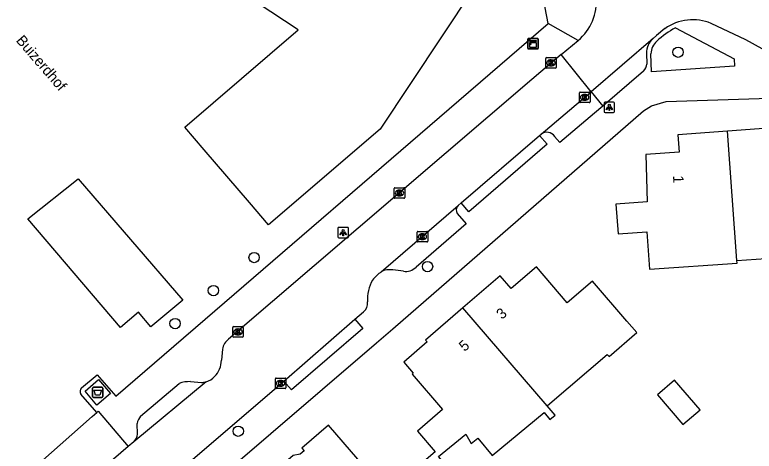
# Model space of a CAD drawing. Extents: x 161772 to 163123, y 383092 to 383917.
# Drawn here: x 162365 to 162435.2, y 383442.3 to 383483.7 of the extents above; entities that cross this region are included whole.
import ezdxf

# ---------------------------------------------------------------- set-up
doc = ezdxf.new("R2010")
doc.units = 0
for name, color, linetype in [('IMGEO_Afval_apart_plaats', 7, 'Continuous'), ('IMGEO_Boom', 7, 'Continuous'), ('IMGEO_Kast', 7, 'Continuous'), ('IMGEO_Kolk', 7, 'Continuous'), ('IMGEO_Lichtpunt', 7, 'Continuous'), ('IMGEO_Openbare_ruimte_label', 7, 'Continuous'), ('IMGEO_Pand', 7, 'Continuous'), ('IMGEO_Pand_nummerreeks', 7, 'Continuous'), ('IMGEO_Parkeervlak_open', 7, 'Continuous'), ('IMGEO_Rijbaan_lokaal_open', 7, 'Continuous'), ('IMGEO_Voetpad_gesloten', 7, 'Continuous'), ('IMGEO_Voetpad_open', 7, 'Continuous')]:
    doc.layers.add(name, color=color, linetype=linetype)

msp = doc.modelspace()

# ---------------------------------------------------------------- linework, layer by layer
at = {"layer": 'IMGEO_Afval_apart_plaats'}
for p, q in [((162372.391, 383447.489), (162372.391, 383448.289)), ((162372.391, 383448.289), (162372.391, 383447.489)), ((162372.491, 383448.389), (162373.281, 383448.389)), ((162373.281, 383448.389), (162372.491, 383448.389)), ((162373.381, 383448.289), (162373.381, 383447.489)), ((162373.381, 383447.489), (162373.381, 383448.289)), ((162373.281, 383447.389), (162372.491, 383447.389)), ((162372.491, 383447.389), (162373.281, 383447.389))]:
    msp.add_line(p, q, dxfattribs=at)
msp.add_lwpolyline([(162372.534, 383448.103), (162373.238, 383448.103), (162373.089, 383447.633), (162372.683, 383447.633), (162372.534, 383448.103)], dxfattribs=at)
for centre, start, end in [((162372.491, 383448.289), 90, 180), ((162372.491, 383448.289), 90, 180), ((162373.281, 383448.289), 0, 90), ((162373.281, 383448.289), 360, 90), ((162372.491, 383447.489), 180, 270), ((162372.491, 383447.489), 180, 270), ((162373.281, 383447.489), 270, 0), ((162373.281, 383447.489), 270, 0)]:
    msp.add_arc(centre, 0.1, start, end, dxfattribs=at)
at = {"layer": 'IMGEO_Boom'}
for centre in [(162427.934, 383480.13), (162387.719, 383460.671), (162404.167, 383459.81), (162383.853, 383457.532), (162380.217, 383454.408), (162386.214, 383444.207)]:
    msp.add_circle(centre, 0.489, dxfattribs=at)
at = {"layer": 'IMGEO_Kast'}
for p, q in [((162413.672, 383480.516), (162413.672, 383481.357)), ((162413.672, 383481.357), (162413.672, 383480.516)), ((162413.747, 383481.441), (162414.588, 383481.441)), ((162414.588, 383481.441), (162413.747, 383481.441)), ((162414.672, 383481.366), (162414.672, 383480.525)), ((162414.672, 383480.525), (162414.672, 383481.366)), ((162414.597, 383480.441), (162413.756, 383480.441)), ((162413.756, 383480.441), (162414.597, 383480.441))]:
    msp.add_line(p, q, dxfattribs=at)
for points in [[(162413.867, 383481.231), (162414.467, 383481.231), (162414.467, 383481.146), (162413.867, 383481.146), (162413.867, 383481.231)], [(162413.867, 383481.056), (162414.467, 383481.056), (162414.467, 383480.567), (162413.867, 383480.567), (162413.867, 383481.056)]]:
    msp.add_lwpolyline(points, dxfattribs=at)
msp.add_circle((162413.951, 383480.905), 0.0377, dxfattribs=at)
for centre, start, end in [((162413.75, 383481.363), 92.4484, 184.28452), ((162413.75, 383481.363), 92.4484, 184.28452), ((162414.594, 383481.363), 2.4484, 94.28452), ((162414.594, 383481.363), 2.4484, 94.28452), ((162413.75, 383480.519), 182.4484, 274.28452), ((162413.75, 383480.519), 182.4484, 274.28452), ((162414.594, 383480.519), 272.4484, 4.28452), ((162414.594, 383480.519), 272.4484, 4.28452)]:
    msp.add_arc(centre, 0.0779, start, end, dxfattribs=at)
at = {"layer": 'IMGEO_Kolk'}
for p, q in [((162415.38, 383478.699), (162415.38, 383479.551)), ((162415.455, 383479.625), (162416.307, 383479.625)), ((162415.868, 383479.405), (162415.893, 383479.405)), ((162416.381, 383479.551), (162416.381, 383478.699)), ((162416.307, 383478.625), (162415.455, 383478.625)), ((162415.891, 383478.845), (162415.866, 383478.845)), ((162418.656, 383476.354), (162419.508, 383476.354)), ((162418.581, 383475.428), (162418.581, 383476.28)), ((162419.069, 383476.134), (162419.094, 383476.134)), ((162419.582, 383476.28), (162419.582, 383475.428)), ((162419.508, 383475.354), (162418.656, 383475.354)), ((162419.092, 383475.574), (162419.067, 383475.574)), ((162401.078, 383467.286), (162401.93, 383467.286)), ((162401.003, 383466.36), (162401.003, 383467.212)), ((162401.491, 383467.066), (162401.516, 383467.066)), ((162402.004, 383467.212), (162402.004, 383466.36)), ((162401.93, 383466.286), (162401.078, 383466.286)), ((162401.514, 383466.506), (162401.489, 383466.506)), ((162403.183, 383462.225), (162403.183, 383463.077)), ((162403.258, 383463.151), (162404.11, 383463.151)), ((162404.184, 383463.077), (162404.184, 383462.225)), ((162403.694, 383462.371), (162403.669, 383462.371)), ((162403.671, 383462.931), (162403.696, 383462.931)), ((162404.11, 383462.151), (162403.258, 383462.151)), ((162385.69, 383453.198), (162385.69, 383454.05)), ((162385.765, 383454.124), (162386.617, 383454.124)), ((162386.178, 383453.904), (162386.203, 383453.904)), ((162386.691, 383454.05), (162386.691, 383453.198)), ((162386.201, 383453.344), (162386.176, 383453.344)), ((162386.617, 383453.124), (162385.765, 383453.124)), ((162389.731, 383448.315), (162389.731, 383449.167)), ((162389.806, 383449.241), (162390.658, 383449.241)), ((162390.219, 383449.021), (162390.244, 383449.021)), ((162390.732, 383449.167), (162390.732, 383448.315)), ((162390.242, 383448.461), (162390.217, 383448.461)), ((162390.658, 383448.241), (162389.806, 383448.241))]:
    msp.add_line(p, q, dxfattribs=at)
for points in [[(162415.38, 383478.699), (162415.38, 383479.551)], [(162415.455, 383479.625), (162416.307, 383479.625)], [(162415.701, 383479.325), (162415.824, 383479.325), (162415.824, 383479.174), (162415.954, 383479.325), (162416.118, 383479.325), (162415.972, 383479.174), (162416.125, 383478.925), (162415.973, 383478.925), (162415.888, 383479.089), (162415.824, 383479.022), (162415.824, 383478.925), (162415.701, 383478.925), (162415.701, 383479.325)], [(162416.381, 383479.551), (162416.381, 383478.699)], [(162416.307, 383478.625), (162415.455, 383478.625)], [(162418.656, 383476.354), (162419.508, 383476.354)], [(162418.581, 383475.428), (162418.581, 383476.28)], [(162418.902, 383476.054), (162419.025, 383476.054), (162419.025, 383475.903), (162419.155, 383476.054), (162419.319, 383476.054), (162419.173, 383475.903), (162419.326, 383475.654), (162419.174, 383475.654), (162419.089, 383475.818), (162419.025, 383475.751), (162419.025, 383475.654), (162418.902, 383475.654), (162418.902, 383476.054)], [(162419.582, 383476.28), (162419.582, 383475.428)], [(162419.508, 383475.354), (162418.656, 383475.354)], [(162401.078, 383467.286), (162401.93, 383467.286)], [(162401.003, 383466.36), (162401.003, 383467.212)], [(162401.324, 383466.986), (162401.447, 383466.986), (162401.447, 383466.835), (162401.577, 383466.986), (162401.741, 383466.986), (162401.595, 383466.835), (162401.748, 383466.586), (162401.596, 383466.586), (162401.511, 383466.75), (162401.447, 383466.683), (162401.447, 383466.586), (162401.324, 383466.586), (162401.324, 383466.986)], [(162402.004, 383467.212), (162402.004, 383466.36)], [(162401.93, 383466.286), (162401.078, 383466.286)], [(162403.183, 383462.225), (162403.183, 383463.077)], [(162403.258, 383463.151), (162404.11, 383463.151)], [(162404.184, 383463.077), (162404.184, 383462.225)], [(162403.504, 383462.851), (162403.627, 383462.851), (162403.627, 383462.7), (162403.757, 383462.851), (162403.921, 383462.851), (162403.775, 383462.7), (162403.928, 383462.451), (162403.776, 383462.451), (162403.691, 383462.615), (162403.627, 383462.548), (162403.627, 383462.451), (162403.504, 383462.451), (162403.504, 383462.851)], [(162404.11, 383462.151), (162403.258, 383462.151)], [(162385.69, 383453.198), (162385.69, 383454.05)], [(162385.765, 383454.124), (162386.617, 383454.124)], [(162386.691, 383454.05), (162386.691, 383453.198)], [(162386.011, 383453.824), (162386.134, 383453.824), (162386.134, 383453.673), (162386.264, 383453.824), (162386.428, 383453.824), (162386.282, 383453.673), (162386.435, 383453.424), (162386.283, 383453.424), (162386.198, 383453.588), (162386.134, 383453.521), (162386.134, 383453.424), (162386.011, 383453.424), (162386.011, 383453.824)], [(162386.617, 383453.124), (162385.765, 383453.124)], [(162389.731, 383448.315), (162389.731, 383449.167)], [(162389.806, 383449.241), (162390.658, 383449.241)], [(162390.732, 383449.167), (162390.732, 383448.315)], [(162390.052, 383448.941), (162390.175, 383448.941), (162390.175, 383448.79), (162390.305, 383448.941), (162390.469, 383448.941), (162390.323, 383448.79), (162390.476, 383448.541), (162390.324, 383448.541), (162390.239, 383448.705), (162390.175, 383448.638), (162390.175, 383448.541), (162390.052, 383448.541), (162390.052, 383448.941)], [(162390.658, 383448.241), (162389.806, 383448.241)]]:
    msp.add_lwpolyline(points, dxfattribs=at)
for centre, start, end in [((162415.457, 383479.549), 91.55205, 178.44795), ((162415.457, 383479.549), 91.55205, 178.44795), ((162416.305, 383479.549), 1.55205, 88.44795), ((162416.305, 383479.549), 1.55205, 88.44795), ((162415.457, 383478.701), 181.55205, 268.44795), ((162415.457, 383478.701), 181.55205, 268.44795), ((162416.305, 383478.701), 271.55205, 358.44795), ((162416.305, 383478.701), 271.55205, 358.44795), ((162418.658, 383476.278), 91.55205, 178.44795), ((162418.658, 383476.278), 91.55205, 178.44795), ((162419.506, 383476.278), 1.55205, 88.44795), ((162419.506, 383476.278), 1.55205, 88.44795), ((162418.658, 383475.43), 181.55205, 268.44795), ((162418.658, 383475.43), 181.55205, 268.44795), ((162419.506, 383475.43), 271.55205, 358.44795), ((162419.506, 383475.43), 271.55205, 358.44795), ((162401.08, 383467.21), 91.55205, 178.44795), ((162401.08, 383467.21), 91.55205, 178.44795), ((162401.928, 383467.21), 1.55205, 88.44795), ((162401.928, 383467.21), 1.55205, 88.44795), ((162401.08, 383466.362), 181.55205, 268.44795), ((162401.08, 383466.362), 181.55205, 268.44795), ((162401.928, 383466.362), 271.55205, 358.44795), ((162401.928, 383466.362), 271.55205, 358.44795), ((162403.26, 383463.075), 91.55205, 178.44795), ((162403.26, 383463.075), 91.55205, 178.44795), ((162404.108, 383463.075), 1.55205, 88.44795), ((162404.108, 383463.075), 1.55205, 88.44795), ((162403.26, 383462.227), 181.55205, 268.44795), ((162403.26, 383462.227), 181.55205, 268.44795), ((162404.108, 383462.227), 271.55205, 358.44795), ((162404.108, 383462.227), 271.55205, 358.44795), ((162385.767, 383454.048), 91.55205, 178.44795), ((162385.767, 383454.048), 91.55205, 178.44795), ((162386.615, 383454.048), 1.55205, 88.44795), ((162386.615, 383454.048), 1.55205, 88.44795), ((162385.767, 383453.2), 181.55205, 268.44795), ((162385.767, 383453.2), 181.55205, 268.44795), ((162386.615, 383453.2), 271.55205, 358.44795), ((162386.615, 383453.2), 271.55205, 358.44795), ((162389.808, 383449.165), 91.55205, 178.44795), ((162389.808, 383449.165), 91.55205, 178.44795), ((162390.656, 383449.165), 1.55205, 88.44795), ((162390.656, 383449.165), 1.55205, 88.44795), ((162389.808, 383448.317), 181.55205, 268.44795), ((162389.808, 383448.317), 181.55205, 268.44795), ((162390.656, 383448.317), 271.55205, 358.44795), ((162390.656, 383448.317), 271.55205, 358.44795)]:
    msp.add_arc(centre, 0.0765, start, end, dxfattribs=at)
for centre, major_axis, ratio, start_param, end_param in [((162415.867, 383479.125), (-0.387, 0.002), 0.722429, 4.712389, 7.853982), ((162415.892, 383479.125), (-0.39, 0.002), 0.717154, 1.570796, 4.712389), ((162419.068, 383475.854), (-0.387, 0.002), 0.722429, 4.712389, 7.853982), ((162419.093, 383475.854), (-0.39, 0.002), 0.717154, 1.570796, 4.712389), ((162401.49, 383466.786), (-0.387, 0.002), 0.722429, 4.712389, 7.853982), ((162401.515, 383466.786), (-0.39, 0.002), 0.717154, 1.570796, 4.712389), ((162403.67, 383462.651), (-0.387, 0.002), 0.722429, 4.712389, 7.853982), ((162403.695, 383462.651), (-0.39, 0.002), 0.717154, 1.570796, 4.712389), ((162386.177, 383453.624), (-0.387, 0.002), 0.722429, 4.712389, 7.853982), ((162386.202, 383453.624), (-0.39, 0.002), 0.717154, 1.570796, 4.712389), ((162390.218, 383448.741), (-0.387, 0.002), 0.722429, 4.712389, 7.853982), ((162390.243, 383448.741), (-0.39, 0.002), 0.717154, 1.570796, 4.712389)]:
    msp.add_ellipse(centre, major_axis=major_axis, ratio=ratio, start_param=start_param, end_param=end_param, dxfattribs=at)
at = {"layer": 'IMGEO_Lichtpunt'}
for p, q in [((162420.912, 383475.308), (162420.912, 383474.501)), ((162420.912, 383475.308), (162420.912, 383474.501)), ((162421.814, 383475.403), (162421.006, 383475.403)), ((162421.814, 383475.403), (162421.006, 383475.403)), ((162421.908, 383474.501), (162421.908, 383475.308)), ((162421.908, 383474.501), (162421.908, 383475.308)), ((162421.006, 383474.407), (162421.814, 383474.407)), ((162421.006, 383474.407), (162421.814, 383474.407)), ((162395.663, 383463.434), (162395.663, 383462.627)), ((162395.663, 383463.434), (162395.663, 383462.627)), ((162396.565, 383463.529), (162395.757, 383463.529)), ((162396.565, 383463.529), (162395.757, 383463.529)), ((162396.659, 383462.627), (162396.659, 383463.434)), ((162396.659, 383462.627), (162396.659, 383463.434)), ((162395.757, 383462.533), (162396.565, 383462.533)), ((162395.757, 383462.533), (162396.565, 383462.533))]:
    msp.add_line(p, q, dxfattribs=at)
for points in [[(162421.286, 383474.972), (162421.325, 383474.944), (162421.137, 383474.682), (162421.099, 383474.709), (162421.286, 383474.972)], [(162421.498, 383474.944), (162421.536, 383474.971), (162421.723, 383474.709), (162421.684, 383474.681), (162421.498, 383474.944)], [(162421.388, 383474.924), (162421.435, 383474.924), (162421.435, 383474.602), (162421.388, 383474.602), (162421.388, 383474.924)], [(162396.037, 383463.098), (162396.076, 383463.07), (162395.888, 383462.808), (162395.85, 383462.835), (162396.037, 383463.098)], [(162396.139, 383463.05), (162396.186, 383463.05), (162396.186, 383462.728), (162396.139, 383462.728), (162396.139, 383463.05)], [(162396.249, 383463.07), (162396.287, 383463.097), (162396.474, 383462.835), (162396.435, 383462.807), (162396.249, 383463.07)]]:
    msp.add_lwpolyline(points, dxfattribs=at)
for centre in [(162421.411, 383475.106), (162396.162, 383463.232)]:
    msp.add_circle(centre, 0.0994, dxfattribs=at)
for centre, start, end in [((162421.006, 383475.308), 90, 180), ((162421.006, 383475.308), 90, 180), ((162421.814, 383475.308), 0, 90), ((162421.814, 383475.308), 0, 90), ((162421.006, 383474.501), 180, 270), ((162421.006, 383474.501), 180, 270), ((162421.814, 383474.501), 270, 0), ((162421.814, 383474.501), 270, 360), ((162395.757, 383463.434), 90, 180), ((162395.757, 383463.434), 90, 180), ((162396.565, 383463.434), 0, 90), ((162396.565, 383463.434), 0, 90), ((162395.757, 383462.627), 180, 270), ((162395.757, 383462.627), 180, 270), ((162396.565, 383462.627), 270, 0), ((162396.565, 383462.627), 270, 360)]:
    msp.add_arc(centre, 0.0946, start, end, dxfattribs=at)
at = {"layer": 'IMGEO_Pand'}
for points in [[(162369.386, 383510.049), (162369.936, 383509.674), (162370.747, 383510.9), (162387.282, 383500), (162408.441, 383486.052), (162399.683, 383472.842), (162389.098, 383463.766), (162387.275, 383465.894), (162382.993, 383470.891), (162381.153, 383473.039), (162391.903, 383482.254), (162364.962, 383500), (162363.969, 383500.654), (162365.459, 383502.906), (162364.939, 383503.25)], [(162433.509, 383460.4), (162438.104, 383460.718), (162437.964, 383462.769), (162441.093, 383462.985), (162441.01, 383464.205), (162444.179, 383464.424), (162443.972, 383467.263), (162440.898, 383467.039), (162440.572, 383471.53), (162437.457, 383471.303), (162437.334, 383472.987), (162432.62, 383472.644)], [(162432.62, 383472.644), (162427.906, 383472.301), (162428.025, 383470.663), (162424.876, 383470.434), (162425.015, 383465.957), (162422.044, 383465.741), (162422.25, 383462.907), (162424.984, 383463.096), (162425.228, 383459.567), (162433.528, 383460.14), (162433.509, 383460.4)], [(162433.509, 383460.4), (162432.62, 383472.644)], [(162366.24, 383464.349), (162371.032, 383468.131), (162380.962, 383456.617), (162377.919, 383454.106), (162376.741, 383455.483), (162375.055, 383454.041), (162366.24, 383464.349)], [(162415.511, 383446.6), (162415.777, 383446.828), (162421.218, 383451.492), (162421.387, 383451.296), (162424.009, 383453.55), (162423.069, 383454.644), (162419.81, 383458.436), (162417.42, 383456.382), (162414.5, 383459.779), (162412.109, 383457.724), (162411.064, 383458.941), (162407.521, 383455.896)], [(162407.521, 383455.896), (162403.978, 383452.85), (162404.138, 383452.663), (162401.908, 383450.746), (162402.803, 383449.706), (162402.705, 383449.621), (162405.603, 383446.25), (162403.213, 383444.195), (162404.883, 383442.252), (162402.53, 383440.23)], [(162415.511, 383446.6), (162407.521, 383455.896)], [(162425.976, 383447.651), (162428.387, 383444.826), (162430.02, 383446.22), (162427.609, 383449.044), (162425.976, 383447.651)], [(162406.239, 383435.919), (162408.561, 383437.915), (162405.218, 383441.804), (162407.793, 383443.937), (162408.314, 383443.038), (162408.934, 383443.551), (162410.299, 383441.903), (162415.22, 383445.98), (162415.768, 383445.318), (162416.262, 383445.727), (162415.511, 383446.6)], [(162402.53, 383440.23), (162400.324, 383438.334), (162394.787, 383444.777), (162392.257, 383442.602), (162392.473, 383442.35), (162392.095, 383442.025), (162391.433, 383441.901), (162390.252, 383440.885), (162390.079, 383440.394), (162389.436, 383439.841)]]:
    msp.add_lwpolyline(points, dxfattribs=at)
at = {"layer": 'IMGEO_Parkeervlak_open'}
msp.add_lwpolyline([(162419.696, 383476.386), (162420.796, 383475.022)], dxfattribs=at)
at = {"layer": 'IMGEO_Rijbaan_lokaal_open'}
for points in [[(162438.997, 383478.75), (162434.351, 383481.292), (162431.078, 383482.869)], [(162426.676, 383482.365), (162425.884, 383481.71), (162425.569, 383481.448)], [(162416.859, 383479.904), (162418.449, 383481.247)], [(162425.569, 383481.448), (162419.696, 383476.386)], [(162416.859, 383479.904), (162414.073, 383477.55), (162385.302, 383452.939)], [(162419.696, 383476.386), (162416.859, 383479.904)], [(162414.94, 383472.377), (162419.084, 383475.858), (162419.696, 383476.386)], [(162407.357, 383465.847), (162414.792, 383472.249)], [(162414.792, 383472.249), (162414.94, 383472.377)], [(162407.071, 383465.599), (162407.357, 383465.847)], [(162399.777, 383459.32), (162407.071, 383465.599)], [(162397.285, 383454.823), (162398.09, 383455.524)], [(162390.543, 383448.958), (162397.285, 383454.823)], [(162384.733, 383451.97), (162384.617, 383450.932)], [(162383.173, 383448.886), (162376.311, 383443.199)], [(162379.009, 383439.051), (162390.543, 383448.958)], [(162375.782, 383442.749), (162370.216, 383437.943)], [(162376.311, 383443.199), (162375.782, 383442.749)]]:
    msp.add_lwpolyline(points, dxfattribs=at)
for centre, radius, start, end in [((162415.493, 383484.886), 4.688, 309.08784, 62.55298), ((162429.342, 383478.555), 4.65, 68.079, 124.9841), ((162402.436, 383455.746), 4.455, 126.64551, 141.36673), ((162402.147, 383456.69), 3.682, 150.07535, 183.50557), ((162397.416, 383456.346), 1.063, 309.36065, 6.44985), ((162386.08, 383451.831), 1.354, 125.06008, 174.09672), ((162382.418, 383450.956), 2.199, 314.52394, 359.37479), ((162382.719, 383450.465), 1.643, 286.02969, 319.03509)]:
    msp.add_arc(centre, radius, start, end, dxfattribs=at)
at = {"layer": 'IMGEO_Voetpad_gesloten'}
msp.add_lwpolyline([(162372.806, 383446.685), (162371.685, 383448.009), (162372.966, 383449.093), (162374.087, 383447.769), (162372.806, 383446.685)], dxfattribs=at)
at = {"layer": 'IMGEO_Voetpad_open'}
for points in [[(162415.606, 383482.867), (162415.154, 383485.181), (162392.934, 383500), (162369.796, 383515.431)], [(162371.354, 383448.328), (162372.821, 383449.539), (162374.592, 383447.522), (162415.606, 383482.867)], [(162418.449, 383481.247), (162415.606, 383482.867)], [(162427.69, 383482.44), (162433.243, 383479.512), (162433.295, 383478.799)], [(162424.937, 383480.039), (162424.966, 383479.012)], [(162433.295, 383478.799), (162425.407, 383478.263), (162425.36, 383479.992)], [(162424.661, 383478.342), (162420.796, 383475.022)], [(162318.405, 383382.124), (162328.478, 383391.862), (162399.336, 383452.584), (162400.868, 383453.897), (162424.669, 383474.563), (162425.429, 383475.046), (162426.801, 383475.456), (162439.546, 383475.883)], [(162420.796, 383475.022), (162420.011, 383474.348), (162416.706, 383471.559), (162416.228, 383472.148)], [(162414.792, 383472.249), (162415.51, 383471.416), (162408.075, 383465.014), (162407.357, 383465.847)], [(162406.991, 383464.837), (162407.828, 383463.86), (162403.075, 383459.764)], [(162401.881, 383459.368), (162400.871, 383459.497)], [(162397.285, 383454.823), (162398.04, 383453.946), (162391.261, 383448.124), (162390.543, 383448.958)], [(162376.954, 383445.633), (162380.6, 383448.744)], [(162381.679, 383448.906), (162382.738, 383448.824)], [(162372.79, 383445.969), (162371.273, 383447.707)], [(162367.39, 383441.216), (162372.358, 383445.597), (162372.79, 383445.969)], [(162372.79, 383445.969), (162372.937, 383446.096), (162375.782, 383442.749)], [(162376.653, 383443.929), (162376.632, 383444.927)]]:
    msp.add_lwpolyline(points, dxfattribs=at)
for centre, radius, start, end in [((162431.822, 383474.726), 8.751, 118.17305, 132.4869), ((162426.777, 383480.06), 1.84, 131.02665, 180.65659), ((162427.154, 383479.881), 1.797, 133.74553, 176.45344), ((162423.851, 383479.115), 1.12, 316.34228, 354.7054), ((162415.468, 383471.611), 0.931, 35.26183, 124.57505), ((162407.463, 383465.173), 0.579, 132.60143, 215.41187), ((162400.61, 383457.644), 1.872, 81.96843, 116.41225), ((162402.093, 383460.727), 1.376, 261.14521, 315.55185), ((162371.738, 383447.962), 0.53, 136.3531, 208.78409), ((162381.591, 383445.817), 3.09, 88.37098, 108.70613), ((162382.733, 383450.419), 1.595, 270.19475, 286.02858), ((162377.858, 383444.794), 1.233, 137.13727, 173.82816), ((162375.578, 383443.988), 1.077, 312.91231, 356.88216)]:
    msp.add_arc(centre, radius, start, end, dxfattribs=at)

# ---------------------------------------------------------------- texts
at = {"layer": 'IMGEO_Openbare_ruimte_label'}
msp.add_text('Buizerdhof', height=1, rotation=310.78157, dxfattribs=at).set_placement((162365.077, 383481.213))
at = {"layer": 'IMGEO_Pand_nummerreeks'}
for s, rotation, p in [('1', 271.77596, (162427.459, 383468.435)), ('3', 40.69441, (162411.223, 383454.751)), ('5', 40.66854, (162407.678, 383451.706))]:
    msp.add_text(s, height=1, rotation=rotation, dxfattribs=at).set_placement(p)

doc.saveas('drawing.dxf')
